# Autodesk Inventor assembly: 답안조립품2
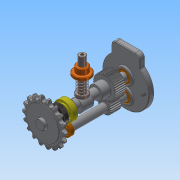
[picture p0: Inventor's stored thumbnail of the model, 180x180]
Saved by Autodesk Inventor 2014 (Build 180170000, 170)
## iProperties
Created: 2016-05
Part Number: 답안조립품2
Document SubType Name: Assembly
Designer: 703-04
Author: 703-04
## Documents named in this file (16)
- C:\Users\703-04\Desktop\360508V1007\답안조립품2.iam
- C:\Users\703-04\Desktop\360508V1007\본체.ipt
- C:\Users\703-04\Desktop\360508V1007\메인축.ipt
- C:\Users\703-04\Desktop\360508V1007\베어링 608.ipt
- C:\Users\703-04\Desktop\360508V1007\베어링 6003.ipt
- C:\Users\703-04\Desktop\360508V1007\키 5 x 5 x 18.ipt
- C:\Users\703-04\Desktop\360508V1007\오일실 8 22 7.ipt
- C:\Users\703-04\Desktop\360508V1007\오일실 17 32 8.ipt
- C:\Users\703-04\Desktop\360508V1007\서브축.ipt
- C:\Users\703-04\Desktop\360508V1007\커버.ipt
- C:\Users\703-04\Desktop\360508V1007\가변 스프링.ipt
- C:\Users\703-04\Desktop\360508V1007\멈춤나사 M3x8.ipt
- C:\Users\703-04\Desktop\360508V1007\부시.ipt
- C:\Users\703-04\Desktop\360508V1007\스프로킷.ipt
- C:\Users\703-04\Desktop\360508V1007\슬라이더.ipt
- C:\Users\703-04\Desktop\360508V1007\볼트 M4 x 10.ipt
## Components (3 placed, 2 different names)
1. 가변 스프링:1
2. ISO 4762 M4 x 10:1
3. ISO 4762 M4 x 10:2
